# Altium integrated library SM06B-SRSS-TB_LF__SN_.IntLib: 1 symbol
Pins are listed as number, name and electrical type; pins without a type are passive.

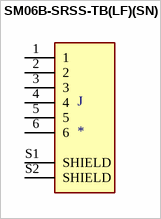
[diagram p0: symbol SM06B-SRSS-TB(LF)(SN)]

## SM06B-SRSS-TB(LF)(SN)
designator J
Connector Header Surface Mount, Right Angle 6 position 0.039 _1.00mm_; MP: SM06B-SRSS-TB_LF__SN_; MF: JST Sales
footprint JST_SM06B-SRSS-TB(LF)(SN)
pins: 1, 2, 3, 4, 5, 6, S1 SHIELD, S2 SHIELD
